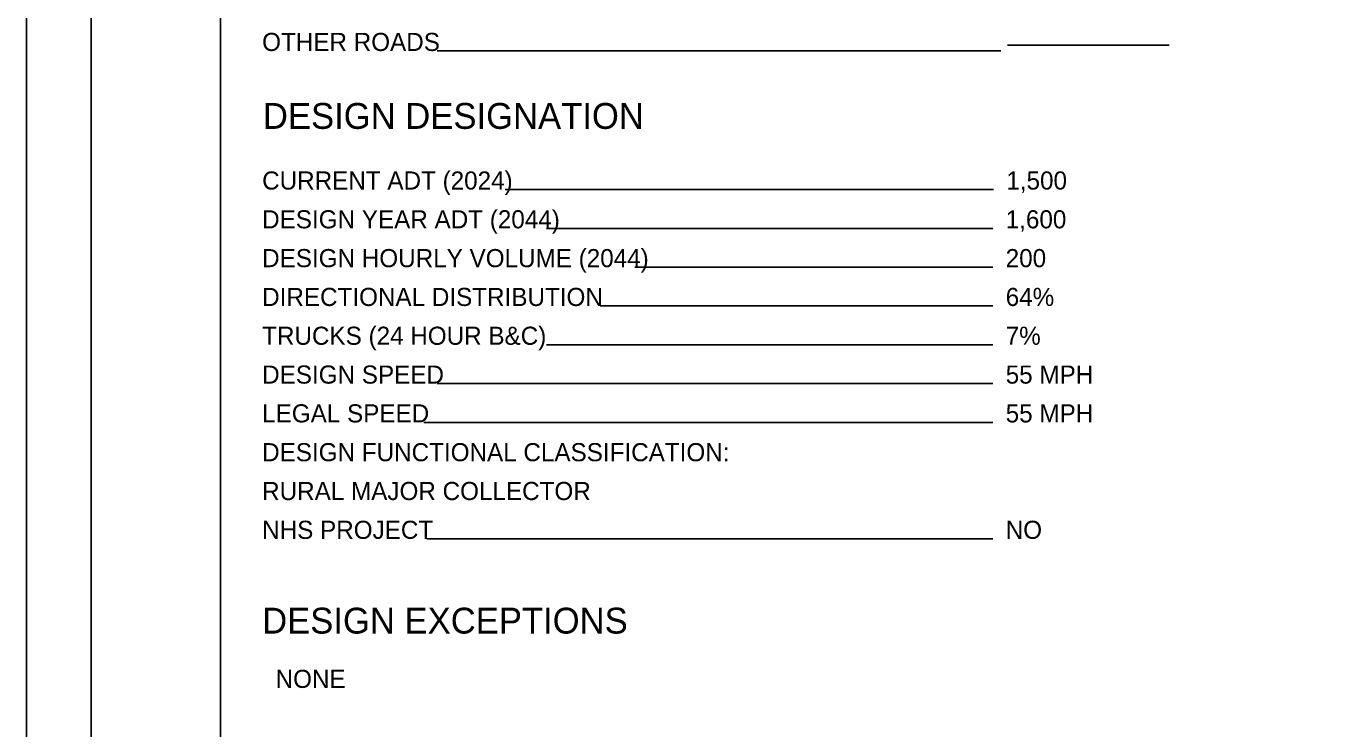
# Model space of a CAD drawing. Extents: x 0 to 34, y 0 to 22.
# Drawn here: x 0 to 10.19, y 5.64 to 11.07 of the extents above; entities that cross this region are included whole.
import ezdxf

# ---------------------------------------------------------------- set-up
doc = ezdxf.new("R2010")
doc.units = 0
for name, color, linetype in [('SH_Border', 7, 'Continuous'), ('SH_Cut_Line', 7, 'Continuous'), ('SH_Data', 7, 'Continuous'), ('SH_Text', 7, 'Continuous')]:
    doc.layers.add(name, color=color, linetype=linetype)

msp = doc.modelspace()

# ---------------------------------------------------------------- linework, layer by layer
at = {"layer": 'SH_Border'}
for points in [[(0.5, 21.5), (1.5, 21.5), (1.5, 0.5), (0.5, 0.5)], [(1.5, 21.5), (33.5, 21.5), (33.5, 0.5), (1.5, 0.5)]]:
    msp.add_lwpolyline(points, close=True, dxfattribs=at)
at = {"layer": 'SH_Cut_Line'}
msp.add_lwpolyline([(0, 0), (34, 0), (34, 22), (0, 22)], close=True, dxfattribs=at)
at = {"layer": 'SH_Data'}
for p, q in [((8.827, 10.922), (7.577, 10.922)), ((7.527, 10.877), (3.174, 10.877)), ((7.469, 9.806), (3.698, 9.806)), ((7.464, 9.506), (4.016, 9.506)), ((7.464, 9.206), (4.699, 9.206)), ((7.464, 8.906), (4.431, 8.906)), ((7.464, 8.606), (4.016, 8.606)), ((7.464, 8.306), (3.173, 8.306)), ((7.464, 8.006), (3.069, 8.006)), ((7.464, 7.106), (3.094, 7.106))]:
    msp.add_line(p, q, dxfattribs=at)

# ---------------------------------------------------------------- texts
msp.add_text('DESIGN DESIGNATION', height=0.2, dxfattribs=at).set_placement((1.827, 10.275))
at = {"layer": 'SH_Text'}
for s, height, p in [('OTHER ROADS', 0.14, (1.821, 10.877)), ('CURRENT ADT (2024)', 0.14, (1.821, 9.806)), ('1,500 ', 0.14, (7.569, 9.806)), ('DESIGN YEAR ADT (2044)', 0.14, (1.821, 9.506)), ('1,600 ', 0.14, (7.564, 9.506)), ('DESIGN HOURLY VOLUME (2044)', 0.14, (1.821, 9.206)), ('200   ', 0.14, (7.564, 9.206)), ('DIRECTIONAL DISTRIBUTION', 0.14, (1.821, 8.906)), ('64%   ', 0.14, (7.564, 8.906)), ('TRUCKS (24 HOUR B&C)', 0.14, (1.821, 8.606)), ('7%    ', 0.14, (7.564, 8.606)), ('DESIGN SPEED', 0.14, (1.821, 8.306)), ('55 MPH', 0.14, (7.564, 8.306)), ('LEGAL SPEED', 0.14, (1.821, 8.006)), ('55 MPH', 0.14, (7.564, 8.006)), ('DESIGN FUNCTIONAL CLASSIFICATION:', 0.14, (1.821, 7.706)), ('RURAL MAJOR COLLECTOR', 0.14, (1.821, 7.406)), ('NHS PROJECT', 0.14, (1.821, 7.106)), ('NO', 0.14, (7.564, 7.106)), ('DESIGN EXCEPTIONS', 0.2, (1.821, 6.374)), ('  NONE                                   ', 0.14, (1.821, 5.954))]:
    msp.add_text(s, height=height, dxfattribs=at).set_placement(p)

doc.saveas('drawing.dxf')
